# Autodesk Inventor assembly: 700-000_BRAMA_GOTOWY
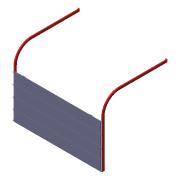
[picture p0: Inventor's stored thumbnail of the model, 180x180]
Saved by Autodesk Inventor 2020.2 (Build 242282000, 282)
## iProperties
Created: 2018-01
Part Number: 700-000_BRAMA_GOTOWY
Document SubType Name: Assembly
Designer: F.Stasiak
Manager: www.cadconsulting.pl
Company: Fabian Stasiak CAD Consulting
Author: F.Stasiak
Subject: Zbiór ćwiczeń. Autodesk Inventor 2020. Kurs podstawowy
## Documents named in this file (5)
- C:\2020_Kurs_podstawowy\R6 Zespoły\Wiązania\Brama\700-000_BRAMA_GOTOWY.iam
- C:\2020_Kurs_podstawowy\R6 Zespoły\Wiązania\Brama\700-001.ipt
- C:\2020_Kurs_podstawowy\R6 Zespoły\Wiązania\Brama\700-002.ipt
- C:\2020_Kurs_podstawowy\R6 Zespoły\Wiązania\Brama\700-003.ipt
- C:\2020_Kurs_podstawowy\R6 Zespoły\Wiązania\Brama\POMOC_1.ipt
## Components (8 placed, 4 different names)
1. 700-001:1 — START, Równoległy:1, Równoległy:2, Przejściowy:1, Przejściowy:2, Równoległy:4, Przejściowy:3, Równoległy:5, Przejściowy:4, Równoległy:6, Przejściowy:5, Zestawiający:6
2. 700-001:2
3. 700-002:1 — START, Równoległy:1, Równoległy:2, Przejściowy:1, Przejściowy:2, Zestawiający:1
4. 700-003:1 — Zestawiający:1, Równoległy:4, Przejściowy:3, Zestawiający:2
5. 700-003:2 — Zestawiający:2, Równoległy:5, Przejściowy:4, Zestawiający:3
6. 700-003:3 — Zestawiający:3, Równoległy:6, Przejściowy:5, Zestawiający:4, Zestawiający:5
7. POMOC_1:1 — Zestawiający:4, Zestawiający:5, Zestawiający:7, STEROWANIE
8. POMOC_1:2 — Zestawiający:6, Zestawiający:7, STEROWANIE
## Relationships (19: Mate 8, Flush 6, Transitional 5)
- STEROWANIE [Mate]: POMOC_1:1 ↔ POMOC_1:2
- START [Flush]: 700-001:1 ↔ 700-002:1
- Równoległy:1 [Flush]: 700-001:1 ↔ 700-002:1
- Równoległy:2 [Flush]: 700-001:1 ↔ 700-002:1
- Przejściowy:1 [Transitional]: 700-001:1 ↔ 700-002:1
- Przejściowy:2 [Transitional]: 700-001:1 ↔ 700-002:1
- Zestawiający:1 [Mate]: 700-002:1 ↔ 700-003:1
- Równoległy:4 [Flush]: 700-001:1 ↔ 700-003:1
- Przejściowy:3 [Transitional]: 700-001:1 ↔ 700-003:1
- Zestawiający:2 [Mate]: 700-003:1 ↔ 700-003:2
- Równoległy:5 [Flush]: 700-001:1 ↔ 700-003:2
- Przejściowy:4 [Transitional]: 700-001:1 ↔ 700-003:2
- Zestawiający:3 [Mate]: 700-003:2 ↔ 700-003:3
- Równoległy:6 [Flush]: 700-001:1 ↔ 700-003:3
- Przejściowy:5 [Transitional]: 700-001:1 ↔ 700-003:3
- Zestawiający:4 [Mate]: 700-003:3 ↔ POMOC_1:1
- Zestawiający:5 [Mate]: 700-003:3 ↔ POMOC_1:1
- Zestawiający:6 [Mate]: 700-001:1 ↔ POMOC_1:2
- Zestawiający:7 [Mate]: POMOC_1:1 ↔ POMOC_1:2
